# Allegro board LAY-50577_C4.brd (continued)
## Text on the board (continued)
User.Comments: 10 | 3 | SECONDARY SOLDMASK | PRIMARY SOLDMASK
TOP: 4 | L1_PS
Ref Des/Silkscreen Top: B | A | C | D | DEVICE | SDP MODE | QSPI FLASH | OCTAL FLASH | SD CARD | SW5 | 0,0,0,1 | 0,1,0,0 | 0,0,1,1 | 2 | PRIMARY SILKSCREEN | MCU-LINK | MIMXRT1180-EVK
L2_GND_1: 5 | L2_GND_1
L3_INT_1: 6 | L3_INT_1
L4_PWR_1: 7 | L4_PWR_1
L5_GND_2: 8 | L5_GND_2
XSECTION_CHART: If the angle of PCB board outline is circular,please use this kind of break out area | If not use it,please delete it before you gerber out | If the angle of PCB board outline is right angle,please use this kind of break out area | AS usual,please use the 0.8MM stamp Via | L1 TOP CONDUCTOR - 1/2OZ_COPPER_PLATED_FOIL | *  DIELECTRIC - TU768 | L2 L2_GND_1 PLANE - 1OZ COPPER | L3 L3_INT_1 CONDUCTOR - 1OZ COPPER | L4 L4_PWR_1 PLANE - 1OZ COPPER | L5 L5_GND_2 PLANE - 1OZ COPPER | L6 BOTTOM CONDUCTOR - 1/2OZ_COPPER_PLATED_FOIL | DESIGN CROSS SECTION CHART | ___________________________ | TOTAL THICKNESS 78.32 MIL | 1-6
DIMENSION: 0 | LAYER STACKUP | DETAIL A
DISPLAY_TOP: BOARD THICKNESS TOLERANCE +/-10% | 19 | 22. | 16. | 1 | IMPEDANCE TOLERANCE IS 10% | DETAIL B | IMPEDANCE REQUIREMENTS
User.5: 12 | SECONDARY PASTEMASK
User.6: 1 | PRIMARY PASTEMASK
User.11: 8 | 5 | 4 | 1 | 3 | 2 | 6 | SOLDMASK TOP
User.12: 8 | 5 | 4 | 1 | 3 | 2 | 6 | SOLDMASK TOP
User.16: 22. THIS FAB_VIAFILL.ART SHOWS LOCATIONS OF VIA_IN_PAD TO BE FILLED. | 2
User.19: 1 | 3 | 2 | 5 | 6 | 60 | 59
User.22: 6501 WILLIAM CANNON DRIVE WEST | AUSTIN. TEXAS 78735 USA | SHEET | THIS DOCUMENT CONTAINS INFORMATION | PROPRIETARY TO FREESCALE AND SHALL | NOT BE USED FOR ENGINEERING DESIGN | PROCUREMENT OR MANUFACTURE IN WHOLE | OR IN PART WITHOUT THE CONSENT OF | NXP. | OF 12 | FILM | NAME | DATE | 05-13-25 | ___ PUBI (PUBLIC INFORMATION) | ___ FIUO (NXP INTERNAL USE ONLY) | ___ FCP (NXP CONFIDENTIAL PROPRIETARY) | NUMBER | X | MIMXRT1180-EVK | 170-50577      REV C4 | NXP SEMICONDUCTOR
User.29: Trace Width | (Mils) | Impedance | (Ohms) | Trace Spacing | "Airgap" | L1 | L3 | L6 | 5.00 | 50 | 5.50 | 48 | 4.2 | 6.00 | 100 | 4.70 | 90 | Layers | Single Ended | Differential
User.30: 1/1 | 03-24-22 | 03-22-23 | 05-08-23 | 06-21-23 | 11-02-23 | 05-13-25 | A.L. | L.P. | 2 | S.C. | J.Z. | B | C | C1 | C2 | C3 | C4 | REVISED RELEASE | UPDATED PER THE SCH REV C | UPDATED PER THE SCH REV C1 | UPDATED PER THE SCH REV C2 | UPDATED PER THE SCH REV C3 | ADDED TP1068~TP1071
User.31: FIGURE | FINISHED_SIZE | 8.0 | 8.1 | 18.0 | 28.0 | 30.0 | 33.0 | 35.0 | 36.0 | 40.0 | 41.0 | 43.0 | 45.0 | 63.0 | 130.0 | 139.0 | 166.0 | 15.0 | 33.5 | 67.0 | 128.0 | 34.0x26.0 | 59.0x33.0 | 79.0x40.0 | 86.61x47.24 | 118.0x31.0 | 137.8x31.5 | DRILL CHART: TOP to BOTTOM | ALL UNITS ARE IN MILS | TOLERANCE_DRILL | +0.0/-8.0 | +0.0/-8.1 | +2.0/-2.0 | +3.0/-3.0 | +1.0/-1.0 | +4.0/-4.0 | PLATED | NON-PLATED | QTY | 2493 | 129 | 3 | 24 | 2 | 34 | 50 | 227 | 12 | 32 | 4 | 20 | 14 | 1 | 6 | 10 | 3105 | TOTAL HOLES:
